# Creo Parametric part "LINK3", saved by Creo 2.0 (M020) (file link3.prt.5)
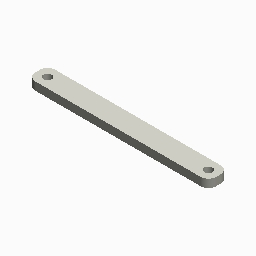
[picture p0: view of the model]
Units: Inch lbm Second (Pro/E Default); INCH, POUND, SECS

Created from: INLBS_PART_SOLID.PRT

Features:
  1. datum plane "RIGHT"
  2. datum plane "TOP"
  3. datum plane "FRONT"
  4. coordinate system
  5. sketch "Sketch 1"
  6. extrusion "Extrude 1", "Sketch 1"
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
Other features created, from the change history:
  datum plane "DTM1"
  datum plane "BOTTON"
  round "Round 1"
